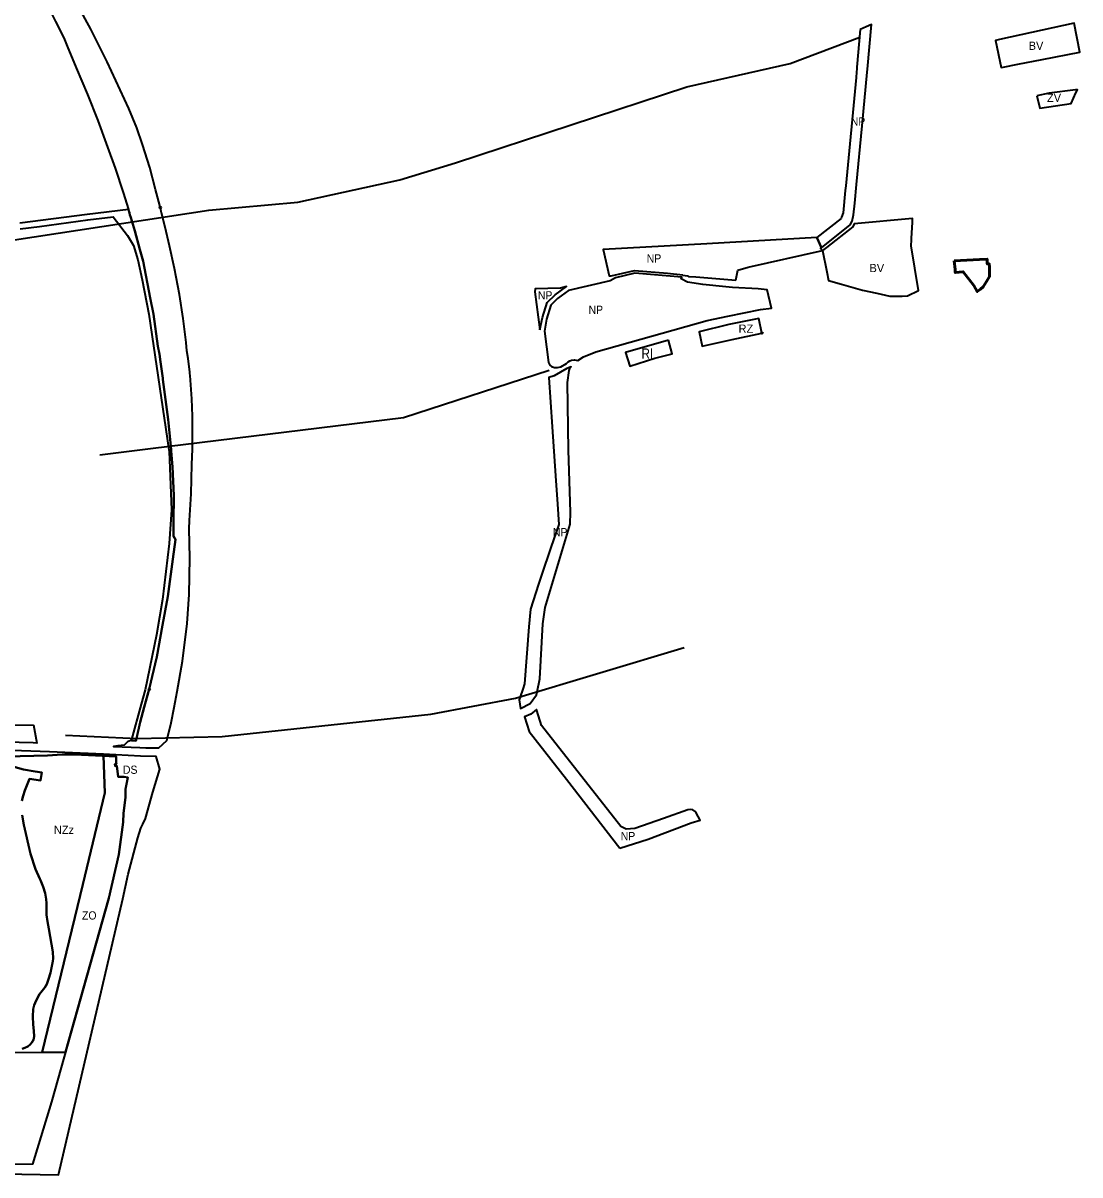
# Model space of a CAD drawing. Extents: x -650276 to -642489, y -1074311 to -1066658.
# Drawn here: x -645218 to -643674, y -1071384 to -1069701 of the extents above; entities that cross this region are included whole.
import ezdxf

# ---------------------------------------------------------------- set-up
doc = ezdxf.new("R2010")
doc.units = 0
doc.header["$LTSCALE"] = 4.8
doc.header["$PDMODE"] = 32
doc.header["$PDSIZE"] = 2.4
for name, color, linetype, lineweight in [('15', 7, 'Continuous', 35), ('24', 7, 'Continuous', 35), ('3', 7, 'Continuous', 35), ('40', 7, 'Continuous', 35), ('42', 7, 'Continuous', 35), ('45', 7, 'Continuous', 35), ('46', 7, 'Continuous', 35), ('48', 7, 'Continuous', 35), ('54', 7, 'Continuous', 35), ('6', 7, 'Continuous', 35), ('60', 7, 'Continuous', 53), ('8', 7, 'Continuous', 35)]:
    doc.layers.add(name, color=color, linetype=linetype, lineweight=lineweight)
doc.layers.add('62', color=7, linetype='Continuous')

msp = doc.modelspace()

# ---------------------------------------------------------------- linework, layer by layer
at = {"layer": '15'}
for points in [[(-645061.76, -1069981.21), (-645064.052, -1069973.429), (-645124.233, -1069980.695), (-645222.809, -1069993.701)], [(-645221.99, -1070001.66), (-645194.003, -1069998.417), (-645123.206, -1069988.629), (-645086.484, -1069984.195), (-645065.235, -1070011.695)], [(-645033.53, -1070674.55), (-645022.64, -1070626.93), (-645014.07, -1070580.72), (-645006.44, -1070538.78), (-644998.92, -1070484.58), (-644995.14, -1070455.72), (-644998.17, -1070450.59), (-644998.25, -1070430.5), (-644997.87, -1070391.16), (-644999.47, -1070349.63), (-645001.64, -1070326.4), (-645001.81, -1070324.58), (-645002.308, -1070319.268), (-645005.98, -1070280.14), (-645013.51, -1070222.04), (-645013.77, -1070220.04), (-645016.92, -1070196.32), (-645018.56, -1070184.92), (-645021.14, -1070173.07), (-645027.49, -1070126.56), (-645032.21, -1070102.73), (-645042.27, -1070049.23), (-645047.28, -1070031.83), (-645054.73, -1070004.56), (-645060.612, -1069985.022), (-645061.76, -1069981.21)], [(-645065.235, -1070011.695), (-645056.555, -1070026.163), (-645050.293, -1070047.035), (-645043.92, -1070076.344), (-645034.122, -1070126.616), (-645004.791, -1070324.889), (-645004.523, -1070326.697)], [(-645004.523, -1070326.697), (-645004.434, -1070327.302), (-645001.312, -1070412.099), (-645004.327, -1070461.264), (-645014.277, -1070543.11), (-645023.048, -1070595.033), (-645039.574, -1070675.065)], [(-645039.574, -1070675.065), (-645045.493, -1070696.321), (-645059.308, -1070747.712), (-645059.403, -1070749.195), (-645053.21, -1070749.75), (-645052.4, -1070746.427), (-645046.63, -1070722.77), (-645041, -1070700.44), (-645033.53, -1070674.55)]]:
    msp.add_lwpolyline(points, dxfattribs=at)
msp.add_point((-645033.53, -1070674.55), dxfattribs=at)
at = {"layer": '24'}
for points in [[(-645322.13, -1069447.96), (-645309.62, -1069467.79), (-645303.57, -1069480.49), (-645268.57, -1069533.23), (-645242.75, -1069570.26), (-645230.42, -1069597.39), (-645227.27, -1069602.68), (-645225.7, -1069605.32), (-645214.76, -1069622.37), (-645198.41, -1069650.49), (-645185.17, -1069673.38), (-645179.12, -1069681.3), (-645170.3, -1069698.91), (-645158.43, -1069722.61), (-645153.44, -1069734.71), (-645140.27, -1069766.68), (-645123.84, -1069805.38), (-645108.74, -1069843.58), (-645094.42, -1069882.65), (-645083.31, -1069913.37), (-645071.53, -1069948.89), (-645063.96, -1069973.73), (-645063.23, -1069976.2), (-645062.57, -1069978.46)], [(-645017.46, -1069970.61), (-645018.28, -1069967.49), (-645024.45, -1069944.43), (-645032.85, -1069912.07), (-645043.5, -1069878.37), (-645051.78, -1069854.2), (-645063.26, -1069825.99), (-645095.1, -1069757.62), (-645118.98, -1069710.08), (-645143.56, -1069664.05), (-645148.8, -1069656.1), (-645150.3, -1069653.84), (-645153.33, -1069649.24), (-645166.67, -1069629), (-645184.88, -1069596.58), (-645202.56, -1069568.23), (-645230.1, -1069525.98)], [(-645062.57, -1069978.46), (-645061.76, -1069981.21), (-645060.612, -1069985.022), (-645054.73, -1070004.56), (-645047.28, -1070031.83), (-645042.27, -1070049.23), (-645032.21, -1070102.73), (-645027.49, -1070126.56), (-645021.14, -1070173.07), (-645018.56, -1070184.92), (-645016.92, -1070196.32), (-645013.77, -1070220.04), (-645013.51, -1070222.04), (-645005.98, -1070280.14), (-645002.308, -1070319.268), (-645001.81, -1070324.58), (-645001.64, -1070326.4), (-644999.47, -1070349.63), (-644997.87, -1070391.16), (-644998.25, -1070430.5), (-644998.17, -1070450.59), (-644995.14, -1070455.72), (-644998.92, -1070484.58), (-645006.44, -1070538.78), (-645014.07, -1070580.72), (-645022.64, -1070626.93), (-645033.53, -1070674.55)], [(-644996.88, -1070059.73), (-645004.02, -1070026.44), (-645010.54, -1069999.3), (-645015.548, -1069978.177), (-645016.01, -1069976.23), (-645016.89, -1069972.82), (-645017.46, -1069970.61)], [(-645033.53, -1070674.55), (-645041, -1070700.44), (-645046.63, -1070722.77), (-645052.4, -1070746.427), (-645053.21, -1070749.75), (-645060.46, -1070749.1), (-645065.17, -1070751.39), (-645070.3, -1070755.92), (-645079.38, -1070756.91), (-645085.58, -1070758.04), (-645047.39, -1070759.71), (-645038.44, -1070759.83), (-645019.57, -1070760.07), (-645007.68, -1070749.5), (-645006.739, -1070745.384), (-645001.71, -1070723.39), (-644997.14, -1070700.88), (-644992.6, -1070677.92), (-644985.04, -1070633.43), (-644978.44, -1070578.56), (-644975.05, -1070536.16), (-644974.44, -1070482.48), (-644975.29, -1070440.14), (-644974.69, -1070427.86), (-644972.48, -1070389.15), (-644971.37, -1070345.98), (-644970.61, -1070323.44), (-644970.55, -1070321.56), (-644970.524, -1070315.358), (-644970.36, -1070275.49), (-644971.47, -1070250.14), (-644974, -1070216.2), (-644974.29, -1070213.17), (-644974.49, -1070210.98), (-644976.94, -1070191.41), (-644978.49, -1070180.05), (-644979.57, -1070167.9), (-644984.21, -1070132.81), (-644989.62, -1070097.79), (-644996.88, -1070059.73)], [(-645327.76, -1071380.76), (-645166.34, -1071384.07), (-645071.99, -1070980.72), (-645064.39, -1070944.7), (-645050.47, -1070891.48), (-645045.74, -1070877.19), (-645043, -1070871.35), (-645039.25, -1070863.33), (-645028.25, -1070824.83), (-645018.18, -1070791.34), (-645023.25, -1070772.62), (-645046.46, -1070771.98), (-645100.32, -1070769.5), (-645156.988, -1070766.884), (-645179.18, -1070765.86), (-645275.8, -1070762.66)], [(-645303, -1070774), (-645182, -1070771), (-645161, -1070770), (-645143, -1070770), (-645081.75, -1070772.79), (-645081.85, -1070781.59), (-645081.57, -1070783.53), (-645083.95, -1070783.89), (-645083.49, -1070786.92), (-645081.13, -1070786.56), (-645081.13, -1070786.56), (-645078.85, -1070802.46), (-645070.2, -1070802.33), (-645065.01, -1070803.22), (-645068.07, -1070820.37), (-645068.52, -1070830.52), (-645068.07, -1070832.72), (-645071.18, -1070855.63), (-645071.77, -1070868.73), (-645078.23, -1070915.65), (-645092.67, -1070979.52), (-645176.14, -1071277.26), (-645204.341, -1071368.19), (-645348.55, -1071370.559)]]:
    msp.add_lwpolyline(points, dxfattribs=at)
msp.add_lwpolyline([(-645202.41, -1070726.571), (-645197.539, -1070753.128), (-645202.96, -1070752.89), (-645285.11, -1070750.69), (-645298.41, -1070751.48), (-645312.2, -1070753.77), (-645325.82, -1070757.94), (-645342.41, -1070765.76), (-645354.98, -1070774.28), (-645398.04, -1070805.44), (-645407.37, -1070810.95), (-645419.18, -1070815.44), (-645426.36, -1070815.78), (-645432.07, -1070816.05), (-645445.81, -1070814.06), (-645429.993, -1070810.647), (-645424.969, -1070809.563), (-645428.39, -1070806.09), (-645430, -1070790.68), (-645428.73, -1070758.67), (-645430.84, -1070751.43), (-645434.53, -1070738.77), (-645435.711, -1070727.497)], close=True, dxfattribs=at)
for p in [(-645017.46, -1069970.61), (-645033.53, -1070674.55)]:
    msp.add_point(p, dxfattribs=at)
at = {"layer": '3'}
for points in [[(-643791.88, -1069725.25), (-643797.75, -1069726.51), (-643789.3, -1069766.05), (-643786.35, -1069765.46), (-643764.94, -1069761.27), (-643729.34, -1069754.3), (-643674.3, -1069743.53), (-643682.61, -1069701.16)], [(-643920.84, -1070026.46), (-643920.29, -1070017.73), (-643920.16, -1070015.69), (-643918.69, -1069992.23), (-643918.88, -1069986.82), (-644004.06, -1069994.59), (-644005.92, -1069998.62), (-644044.7, -1070029.04), (-644050.12, -1070033.64), (-644044.18, -1070064.43), (-644041.71, -1070077.29), (-644022.77, -1070082.66), (-643991.99, -1070091.37), (-643971.03, -1070095.79), (-643951.99, -1070100.35), (-643933.96, -1070100.18), (-643926.33, -1070099.5), (-643909.87, -1070091.95)]]:
    msp.add_lwpolyline(points, close=True, dxfattribs=at)
at = {"layer": '40'}
msp.add_lwpolyline([(-643737.47, -1069807.24), (-643733.02, -1069825.4), (-643687.2, -1069818.8), (-643680.15, -1069803.22), (-643678.02, -1069798.52), (-643680.83, -1069798.86), (-643719.42, -1069803.49)], close=True, dxfattribs=at)
at = {"layer": '42'}
for points in [[(-645155.777, -1071204.626), (-645092.67, -1070979.52), (-645078.23, -1070915.65), (-645071.77, -1070868.73), (-645071.18, -1070855.63), (-645068.07, -1070832.72), (-645068.52, -1070830.52), (-645068.07, -1070820.37), (-645065.01, -1070803.22), (-645070.2, -1070802.33), (-645078.85, -1070802.46), (-645081.13, -1070786.56), (-645081.13, -1070786.56), (-645083.49, -1070786.92), (-645083.95, -1070783.89), (-645081.57, -1070783.53), (-645081.85, -1070781.59), (-645081.75, -1070772.79), (-645100.268, -1070771.946)], [(-645100.268, -1070771.946), (-645098.438, -1070825.558), (-645130.749, -1070959.561)], [(-645130.749, -1070959.561), (-645130.749, -1070959.561), (-645189.902, -1071204.885)], [(-645189.902, -1071204.885), (-645186.64, -1071204.86), (-645155.777, -1071204.626)]]:
    msp.add_lwpolyline(points, dxfattribs=at)
at = {"layer": '45'}
for points in [[(-645219.787, -1070837.502), (-645217.778, -1070830.159), (-645215.063, -1070822.589), (-645208.696, -1070805.535), (-645192.298, -1070807.665), (-645190.59, -1070796.152), (-645200.111, -1070794.621), (-645217.086, -1070791.58), (-645233.003, -1070787.399)], [(-645192.548, -1070953.47), (-645193.51, -1070951.2), (-645199.714, -1070937.126), (-645206.872, -1070914.991), (-645216.991, -1070872.38), (-645219.351, -1070858.481)], [(-645219.283, -1071199.786), (-645215.351, -1071198.562), (-645211.07, -1071196.464), (-645207.575, -1071193.492), (-645205.049, -1071190.531), (-645202.777, -1071186.423), (-645201.903, -1071181.615), (-645202.34, -1071173.66), (-645203.301, -1071164.132), (-645203.738, -1071152.537), (-645202.951, -1071141.698), (-645201.648, -1071136.226), (-645198.678, -1071128.971), (-645193.872, -1071120.142), (-645186.284, -1071110.216), (-645183.401, -1071105.408), (-645180.692, -1071098.24), (-645177.809, -1071088.625), (-645174.225, -1071071.8), (-645173.788, -1071067.691), (-645174.225, -1071057.989), (-645180.164, -1071024.56), (-645182.261, -1071013.633), (-645183.746, -1071003.786), (-645183.833, -1070986.74), (-645184.357, -1070981.146), (-645185.843, -1070972.23), (-645188.377, -1070963.313), (-645192.548, -1070953.47)]]:
    msp.add_lwpolyline(points, dxfattribs=at)
at = {"layer": '46'}
for points in [[(-645346.31, -1071206.07), (-645189.902, -1071204.885), (-645130.749, -1070959.561), (-645098.438, -1070825.558), (-645100.268, -1070771.946), (-645143, -1070770), (-645161, -1070770)], [(-645161, -1070770), (-645182, -1070771), (-645303, -1070774)], [(-645233.003, -1070787.399), (-645217.086, -1070791.58), (-645200.111, -1070794.621), (-645190.59, -1070796.152), (-645192.298, -1070807.665), (-645208.696, -1070805.535), (-645215.063, -1070822.589), (-645217.778, -1070830.159), (-645219.787, -1070837.502)], [(-645219.351, -1070858.481), (-645216.991, -1070872.38), (-645206.872, -1070914.991), (-645199.714, -1070937.126), (-645193.51, -1070951.2), (-645192.548, -1070953.47), (-645188.377, -1070963.313), (-645185.843, -1070972.23), (-645184.357, -1070981.146), (-645183.833, -1070986.74), (-645183.746, -1071003.786), (-645182.261, -1071013.633), (-645180.164, -1071024.56), (-645174.225, -1071057.989), (-645173.788, -1071067.691), (-645173.788, -1071067.691), (-645174.225, -1071071.8), (-645177.809, -1071088.625), (-645180.692, -1071098.24), (-645183.401, -1071105.408), (-645183.401, -1071105.408), (-645186.284, -1071110.216), (-645193.872, -1071120.142), (-645193.872, -1071120.142), (-645198.678, -1071128.971), (-645198.678, -1071128.971), (-645201.648, -1071136.226), (-645202.951, -1071141.698), (-645202.951, -1071141.698), (-645203.738, -1071152.537), (-645203.738, -1071152.537), (-645203.301, -1071164.132), (-645202.34, -1071173.66), (-645201.903, -1071181.615), (-645201.903, -1071181.615), (-645202.777, -1071186.423), (-645202.777, -1071186.423), (-645205.049, -1071190.531), (-645207.575, -1071193.492), (-645207.575, -1071193.492), (-645211.07, -1071196.464), (-645211.07, -1071196.464), (-645215.351, -1071198.562), (-645219.283, -1071199.786)]]:
    msp.add_lwpolyline(points, dxfattribs=at)
at = {"layer": '48'}
for points in [[(-643995.17, -1069710.42), (-643999.94, -1069765.62), (-644000.79, -1069775.42), (-644001.04, -1069778.063), (-644001.29, -1069780.7), (-644016.47, -1069938.99), (-644017.15, -1069945.93), (-644020.26, -1069978.38), (-644022.43, -1069984.87), (-644022.99, -1069986.58), (-644058.55, -1070014.4), (-644051.913, -1070029.549), (-644049.311, -1070027.453), (-644009.95, -1069995.74), (-644006.96, -1069990.34), (-644005.06, -1069981.28), (-644003.06, -1069964.06), (-644000.52, -1069937.19), (-643992.27, -1069851.31), (-643984.845, -1069772.863), (-643984.44, -1069768.58), (-643978.85, -1069703.4), (-643986.744, -1069706.796)], [(-644381.21, -1070181.71), (-644218.65, -1070135.75), (-644188.44, -1070129.43), (-644140.72, -1070119.57), (-644125, -1070117.83), (-644130.91, -1070091.1), (-644144.13, -1070089.47), (-644181.81, -1070087.51), (-644191.26, -1070086.47), (-644225.13, -1070082.95), (-644247.3, -1070079.69), (-644256.54, -1070075.02), (-644255.52, -1070072.5), (-644324.42, -1070066.48), (-644352.71, -1070073.46), (-644360.41, -1070077.91), (-644421.26, -1070091.99), (-644437.34, -1070103.76), (-644447.13, -1070113.11), (-644453.22, -1070133.99), (-644456.41, -1070151.18), (-644450.72, -1070196.97), (-644448.76, -1070200.77), (-644445.9, -1070202.83), (-644441.8, -1070204.26), (-644437.415, -1070204.436), (-644432.53, -1070203.32), (-644424.14, -1070198.29), (-644421.88, -1070196.28), (-644419.51, -1070194.76), (-644416.67, -1070193.7), (-644412.54, -1070193.18), (-644407.55, -1070194.16), (-644399.15, -1070188.55)], [(-644463.28, -1070149.42), (-644459.09, -1070131.08), (-644452.65, -1070109.46), (-644440.64, -1070098.4), (-644423.99, -1070086.17), (-644433.19, -1070088.37), (-644470.17, -1070089.43), (-644470.55, -1070093.61)], [(-644491.691, -1070685.524), (-644491.82, -1070685.92), (-644493.5, -1070689.75), (-644491.42, -1070702.64), (-644477.46, -1070695.09), (-644467.84, -1070682.37), (-644466.998, -1070678.065), (-644463.28, -1070659.06), (-644458.85, -1070579.04), (-644455.2, -1070554.88), (-644418.69, -1070433.36), (-644418.23, -1070415.62), (-644421.45, -1070325.29), (-644422.5, -1070226.42), (-644420.14, -1070208.56), (-644418.61, -1070204.51), (-644417.36, -1070203.24), (-644421.47, -1070204.77), (-644423.66, -1070205.86), (-644442.2, -1070216.72), (-644450.15, -1070219.06), (-644445.28, -1070290.84), (-644440.36, -1070362.62), (-644437.53, -1070404.1), (-644435.51, -1070433.85), (-644447.14, -1070467.28), (-644460.5, -1070507.68), (-644464.98, -1070521.13), (-644476.94, -1070557.45), (-644479.06, -1070583.13), (-644485.64, -1070666.7), (-644488.01, -1070674.2)], [(-644346.21, -1070906.61), (-644305.07, -1070893.39), (-644242.29, -1070869.82), (-644229.12, -1070865.52), (-644234.66, -1070855.08), (-644236.3, -1070852.87), (-644239.47, -1070850.71), (-644243.15, -1070849.89), (-644246.93, -1070850.52), (-644282.77, -1070863.19), (-644324.34, -1070877.71), (-644337.15, -1070878.64), (-644344.86, -1070875.09), (-644460.82, -1070727.21), (-644465.31, -1070713.25), (-644468.1, -1070704.23), (-644476.35, -1070710.99), (-644485.61, -1070714.95), (-644478.67, -1070736.28), (-644424.37, -1070806.03)]]:
    msp.add_lwpolyline(points, close=True, dxfattribs=at)
for points in [[(-644058.55, -1070014.4), (-644219.33, -1070023.53), (-644370.87, -1070032.13), (-644361.74, -1070070.32), (-644359.02, -1070070.67), (-644324.72, -1070062.44), (-644276.85, -1070066.62), (-644254.13, -1070069.08)], [(-644177.01, -1070076.69), (-644177.01, -1070076.69), (-644174.12, -1070062.16), (-644159.02, -1070057.84), (-644050.12, -1070033.64), (-644053.18, -1070030.57), (-644051.913, -1070029.549), (-644058.55, -1070014.4)], [(-644254.13, -1070069.08), (-644254.25, -1070069.37), (-644247.72, -1070070.21), (-644245.9, -1070071.26), (-644235.49, -1070072.08), (-644177.01, -1070076.69)]]:
    msp.add_lwpolyline(points, dxfattribs=at)
at = {"layer": '54'}
for points in [[(-645230.538, -1070017.864), (-644946.741, -1069974.541), (-644816.387, -1069962.572), (-644667.646, -1069930.034), (-644586.303, -1069905.244), (-644248.286, -1069794.155), (-644097.378, -1069760.147), (-643995.653, -1069721.915)], [(-645105.781, -1070331.996), (-645031.648, -1070322.877), (-644662.188, -1070277.428), (-644449.34, -1070208.499)], [(-645155.795, -1070741.501), (-645051.039, -1070746.492), (-644927.167, -1070743.394), (-644622.134, -1070710.86), (-644498.737, -1070687.652), (-644252.543, -1070613.291)]]:
    msp.add_lwpolyline(points, dxfattribs=at)
at = {"layer": '6'}
msp.add_lwpolyline([(-644275.05, -1070164.59), (-644338.06, -1070182.64), (-644331.9, -1070202.4), (-644295.01, -1070190.9), (-644269.84, -1070184.57)], close=True, dxfattribs=at)
at = {"layer": '60'}
msp.add_lwpolyline([(-643858.23, -1070048.35), (-643856.72, -1070061.26), (-643856.49, -1070065.66), (-643844.87, -1070064.51), (-643829.38, -1070084.37), (-643824.22, -1070093.34), (-643819.67, -1070089.82), (-643815.9, -1070086.27), (-643813.21, -1070082.8), (-643810.91, -1070078.63), (-643806.17, -1070071.18), (-643806.59, -1070057.37), (-643806.86, -1070053.03), (-643809.71, -1070053.15), (-643810, -1070046), (-643820.78, -1070046.59)], close=True, dxfattribs=at)
at = {"layer": '8'}
for p, q in [((-644138.78, -1070154.07), (-644143.31, -1070132.95)), ((-644182.31, -1070163.66), (-644138.78, -1070154.07))]:
    msp.add_line(p, q, dxfattribs=at)
msp.add_lwpolyline([(-644143.31, -1070132.95), (-644143.31, -1070132.95), (-644143.31, -1070132.95), (-644187.11, -1070141.58), (-644230.4, -1070152.08), (-644226.23, -1070173.28), (-644182.31, -1070163.66)], dxfattribs=at)
msp.add_point((-644138.78, -1070154.07), dxfattribs=at)

# ---------------------------------------------------------------- texts
at = {"layer": '62'}
for s, p in [('BV', (-643749.135, -1069740.303)), ('ZV', (-643722.385, -1069816.315)), ('BV', (-643981.639, -1070065.037)), ('RZ', (-644172.882, -1070153.612)), ('NZz', (-645172.866, -1070885.823))]:
    msp.add_text(s, height=12, dxfattribs=at).set_placement(p)
for s, height, width, p in [('NP', 12, 0.95, (-644008.985, -1069850.967)), ('NP', 12, 0.95, (-644306.985, -1070050.967)), ('NP', 12, 0.95, (-644465.985, -1070104.967)), ('NP', 12, 0.95, (-644391.985, -1070125.967)), ('RI', 15, 0.85, (-644314.705, -1070191.481)), ('NP', 12, 0.95, (-644444, -1070450.967)), ('DS', 12, 0.95, (-645072.003, -1070798.001)), ('NP', 12, 0.95, (-644345, -1070894.967)), ('ZO', 12, 0.95, (-645131.758, -1071010.853))]:
    msp.add_text(s, height=height, dxfattribs=dict(at, width=width)).set_placement(p)

doc.saveas('drawing.dxf')
